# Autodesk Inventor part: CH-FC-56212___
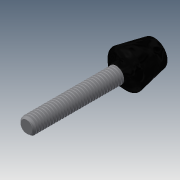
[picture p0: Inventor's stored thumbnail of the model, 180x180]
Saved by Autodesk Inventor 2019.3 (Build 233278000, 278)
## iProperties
Created: 2013-01
Part Number: CH-FC-56212___
Material: Ogólny
Document SubType Name: Modeling
Designer: CADENGINEERING4
Density: 1 g/cm^3
Appearance: Domyślna
Author: CADENGINEERING4
Revision Number: ÈÎºÎ
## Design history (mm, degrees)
feature "NONE"
node "Bryła1"
